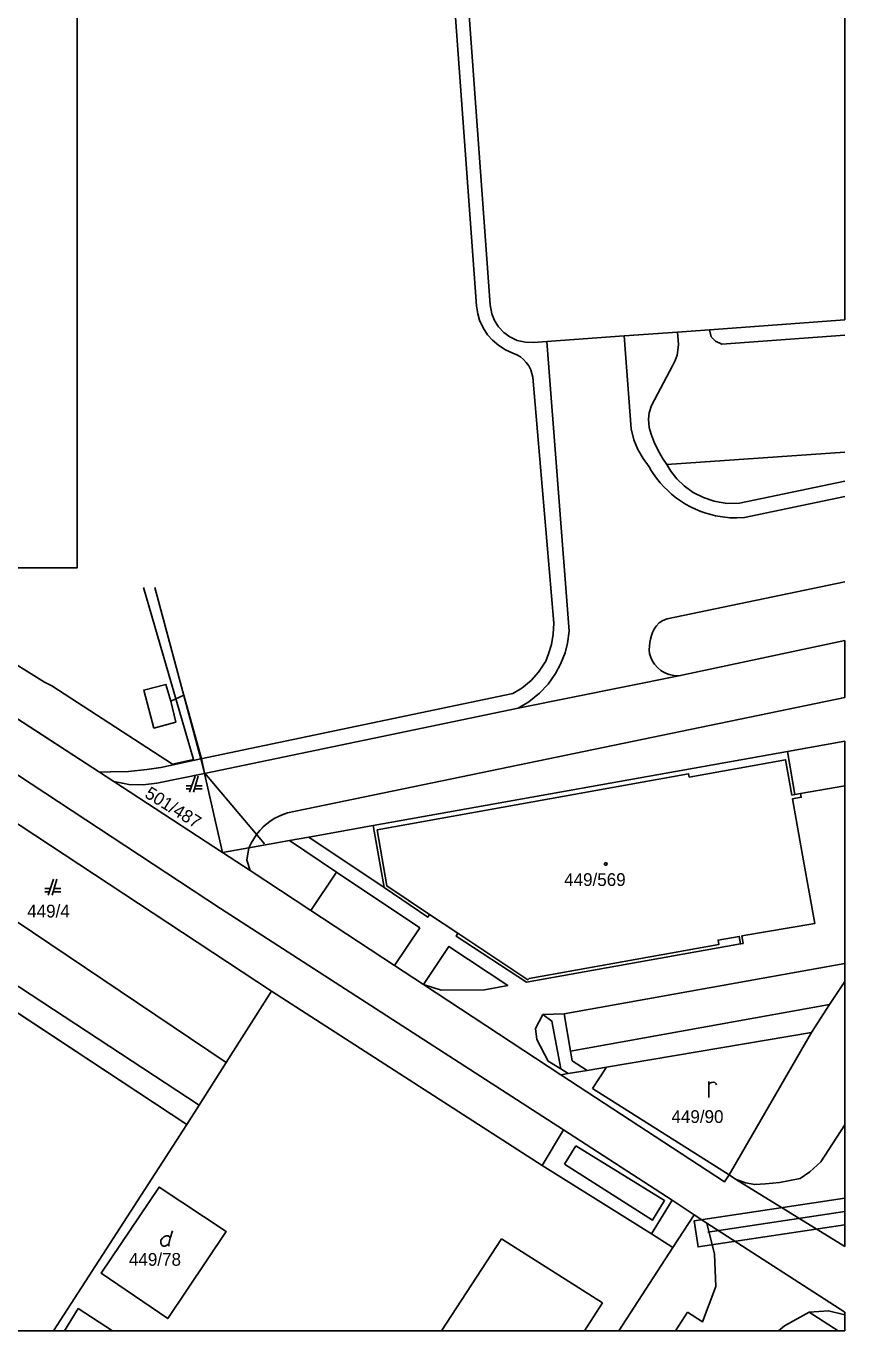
# Model space of a CAD drawing. Extents: x -264309 to -263505, y -1242443 to -1241763.
# Drawn here: x -263692.2 to -263589.3, y -1242443.4 to -1242279.4 of the extents above; entities that cross this region are included whole.
import ezdxf

# ---------------------------------------------------------------- set-up
doc = ezdxf.new("R2010")
doc.units = 0
for name, color, linetype in [('KN_2019_08_16', 7, 'Continuous'), ('KN_2019_08_16_KLADPAR', 7, 'Continuous'), ('KN_2019_08_16_ZAPPAR', 7, 'Continuous'), ('RAM_NA_TLAC_10xA4_1-500', 7, 'Continuous')]:
    doc.layers.add(name, color=color, linetype=linetype)

msp = doc.modelspace()

# ---------------------------------------------------------------- linework, layer by layer
at = {"layer": 'KN_2019_08_16'}
for p, q in [((-263610.2, -1242361.1), (-263589.31, -1242356.66)), ((-263589.31, -1242356.66), (-263589.31, -1242363.85)), ((-263630.41, -1242365.17), (-263610.2, -1242361.1)), ((-263674.06, -1242364.31), (-263672.43, -1242363.55)), ((-263589.31, -1242363.85), (-263659.38, -1242378.34)), ((-263669.82, -1242373.37), (-263630.41, -1242365.17)), ((-263667.55, -1242383.31), (-263669.82, -1242373.37)), ((-263661.45, -1242379.28), (-263662.17, -1242379.84)), ((-263660.98, -1242379), (-263661.45, -1242379.28)), ((-263660.45, -1242378.73), (-263660.98, -1242379)), ((-263659.38, -1242378.34), (-263660.45, -1242378.73)), ((-263663.27, -1242381.05), (-263663.62, -1242381.58)), ((-263662.87, -1242380.54), (-263663.27, -1242381.05)), ((-263662.17, -1242379.84), (-263662.87, -1242380.54)), ((-263664.25, -1242382.72), (-263667.55, -1242383.31)), ((-263663.96, -1242382.14), (-263664.25, -1242382.72)), ((-263663.62, -1242381.58), (-263663.96, -1242382.14))]:
    msp.add_line(p, q, dxfattribs=at)
msp.add_lwpolyline([(-263673.41, -1242366.94), (-263676.19, -1242367.67), (-263677.46, -1242362.89), (-263674.68, -1242362.18), (-263674.06, -1242364.31)], close=True, dxfattribs=at)
for points in [[(-263662.29, -1242382.21), (-263669.81, -1242373.31), (-263670.19, -1242371.53), (-263672.43, -1242363.55)], [(-263683.03, -1242373.21), (-263681.64, -1242373.18), (-263679.37, -1242373.13), (-263677.08, -1242372.9)], [(-263608.27, -1242429.62), (-263589.31, -1242426.78)], [(-263606.54, -1242431.03), (-263589.31, -1242428.45)], [(-263589.31, -1242430.12), (-263607.78, -1242432.89), (-263608.27, -1242429.62)]]:
    msp.add_lwpolyline(points, dxfattribs=at)
at = {"layer": 'KN_2019_08_16_KLADPAR'}
for p, q in [((-263589.31, -1242316.35), (-263589.31, -1242257.5)), ((-263589.31, -1242257.5), (-263589.31, -1242316.35)), ((-263637.43, -1242266.15), (-263633.91, -1242314.48)), ((-263633.91, -1242314.48), (-263637.43, -1242266.15)), ((-263633.91, -1242314.48), (-263633.7, -1242315.61)), ((-263633.7, -1242315.61), (-263633.91, -1242314.48)), ((-263633.7, -1242315.61), (-263633.37, -1242316.46)), ((-263633.37, -1242316.46), (-263633.7, -1242315.61)), ((-263633.37, -1242316.46), (-263632.85, -1242317.25)), ((-263632.85, -1242317.25), (-263633.37, -1242316.46)), ((-263632.85, -1242317.25), (-263632.21, -1242317.94)), ((-263632.21, -1242317.94), (-263632.85, -1242317.25)), ((-263606.35, -1242317.6), (-263589.31, -1242316.35)), ((-263589.31, -1242316.35), (-263606.35, -1242317.6)), ((-263632.21, -1242317.94), (-263631.44, -1242318.5)), ((-263631.44, -1242318.5), (-263632.21, -1242317.94)), ((-263631.44, -1242318.5), (-263630.51, -1242318.94)), ((-263630.51, -1242318.94), (-263631.44, -1242318.5)), ((-263630.51, -1242318.94), (-263629.45, -1242319.18)), ((-263629.45, -1242319.18), (-263630.51, -1242318.94)), ((-263628.43, -1242319.22), (-263626.78, -1242319.09)), ((-263626.78, -1242319.09), (-263628.43, -1242319.22)), ((-263626.78, -1242319.09), (-263617.07, -1242318.38)), ((-263617.07, -1242318.38), (-263626.78, -1242319.09)), ((-263617.07, -1242318.38), (-263610.36, -1242317.89)), ((-263610.36, -1242317.89), (-263617.07, -1242318.38)), ((-263610.36, -1242317.89), (-263606.35, -1242317.6)), ((-263606.35, -1242317.6), (-263610.36, -1242317.89)), ((-263629.45, -1242319.18), (-263628.43, -1242319.22)), ((-263628.43, -1242319.22), (-263629.45, -1242319.18)), ((-263676.05, -1242349.99), (-263670.3, -1242371.56)), ((-263676.05, -1242349.99), (-263670.3, -1242371.56)), ((-263683.03, -1242373.21), (-263697.93, -1242363.54)), ((-263596.55, -1242370.61), (-263589.31, -1242369.32)), ((-263596.55, -1242370.61), (-263589.31, -1242369.32)), ((-263589.31, -1242369.32), (-263589.31, -1242399.51)), ((-263670.3, -1242371.56), (-263675.31, -1242372.61)), ((-263670.3, -1242371.56), (-263670.3, -1242371.56)), ((-263670.3, -1242371.56), (-263669.82, -1242373.37)), ((-263648.63, -1242379.93), (-263596.55, -1242370.61)), ((-263648.63, -1242379.93), (-263596.55, -1242370.61)), ((-263681.64, -1242373.18), (-263683.03, -1242373.21)), ((-263679.37, -1242373.13), (-263681.64, -1242373.18)), ((-263677.08, -1242372.9), (-263679.37, -1242373.13)), ((-263675.31, -1242372.61), (-263677.08, -1242372.9)), ((-263671.01, -1242373.72), (-263671.71, -1242375.72)), ((-263671.21, -1242375.72), (-263670.61, -1242373.72)), ((-263669.82, -1242373.37), (-263667.55, -1242383.31)), ((-263671.43, -1242374.92), (-263672.11, -1242374.92)), ((-263672.11, -1242375.32), (-263671.57, -1242375.32)), ((-263671.09, -1242375.32), (-263670.11, -1242375.32)), ((-263670.11, -1242374.92), (-263670.97, -1242374.92)), ((-263659.13, -1242381.8), (-263656.71, -1242381.37)), ((-263659.13, -1242381.8), (-263656.71, -1242381.37)), ((-263656.71, -1242381.37), (-263648.63, -1242379.93)), ((-263656.71, -1242381.37), (-263648.63, -1242379.93)), ((-263667.55, -1242383.31), (-263664.25, -1242382.72)), ((-263667.55, -1242383.31), (-263664.25, -1242382.72)), ((-263664.25, -1242382.72), (-263659.13, -1242381.8)), ((-263664.25, -1242382.72), (-263659.13, -1242381.8)), ((-263667.55, -1242383.31), (-263667.55, -1242383.31)), ((-263667.55, -1242383.31), (-263667.55, -1242383.31)), ((-263664.1, -1242385.58), (-263667.55, -1242383.31)), ((-263656.46, -1242390.6), (-263664.1, -1242385.58)), ((-263718.68, -1242386.77), (-263672.04, -1242417.52)), ((-263689.21, -1242387.86), (-263689.89, -1242387.86)), ((-263688.79, -1242386.66), (-263689.49, -1242388.66)), ((-263688.99, -1242388.66), (-263688.39, -1242386.66)), ((-263687.89, -1242387.86), (-263688.75, -1242387.86)), ((-263689.89, -1242388.26), (-263689.35, -1242388.26)), ((-263688.87, -1242388.26), (-263687.89, -1242388.26)), ((-263645.94, -1242397.52), (-263656.46, -1242390.6)), ((-263642.28, -1242399.92), (-263645.94, -1242397.52)), ((-263667.1, -1242409.72), (-263661.41, -1242400.75)), ((-263661.41, -1242400.75), (-263661.41, -1242400.75)), ((-263661.41, -1242400.75), (-263661.41, -1242400.75)), ((-263661.41, -1242400.75), (-263661.41, -1242400.75)), ((-263661.41, -1242400.75), (-263661.41, -1242400.75)), ((-263661.41, -1242400.75), (-263661.41, -1242400.75)), ((-263661.41, -1242400.75), (-263627.39, -1242422.66)), ((-263625.01, -1242411.27), (-263642.28, -1242399.92)), ((-263589.31, -1242399.51), (-263591.23, -1242402.42)), ((-263591.23, -1242402.42), (-263589.31, -1242399.51)), ((-263589.31, -1242399.51), (-263589.31, -1242432.83)), ((-263591.23, -1242402.42), (-263593.53, -1242405.92)), ((-263593.53, -1242405.92), (-263591.23, -1242402.42)), ((-263593.53, -1242405.92), (-263619.27, -1242410.29)), ((-263603.88, -1242423.85), (-263593.53, -1242405.92)), ((-263670.49, -1242415.08), (-263667.1, -1242409.72)), ((-263621.71, -1242410.71), (-263624.1, -1242411.11)), ((-263619.27, -1242410.29), (-263621.71, -1242410.71)), ((-263624.1, -1242411.11), (-263625.01, -1242411.27)), ((-263672.04, -1242417.52), (-263670.49, -1242415.08)), ((-263627.39, -1242422.66), (-263613.64, -1242431.25)), ((-263603.08, -1242424.39), (-263603.88, -1242423.85)), ((-263589.31, -1242432.83), (-263603.08, -1242424.39)), ((-263610.94, -1242432.97), (-263608.28, -1242428.86)), ((-263608.28, -1242428.86), (-263606.66, -1242429.9)), ((-263606.66, -1242429.9), (-263589.31, -1242441.09)), ((-263674.12, -1242431.79), (-263673.85, -1242430.89)), ((-263632.48, -1242431.88), (-263640.01, -1242443.45)), ((-263640.01, -1242443.45), (-263632.48, -1242431.88)), ((-263619.78, -1242439.93), (-263632.48, -1242431.88)), ((-263632.48, -1242431.88), (-263619.78, -1242439.93)), ((-263613.64, -1242431.25), (-263610.94, -1242432.97)), ((-263617.74, -1242443.45), (-263610.94, -1242432.97)), ((-263610.94, -1242432.97), (-263617.74, -1242443.45)), ((-263622.04, -1242443.45), (-263619.78, -1242439.93)), ((-263619.78, -1242439.93), (-263622.04, -1242443.45)), ((-263685.72, -1242440.64), (-263687.43, -1242443.45)), ((-263687.43, -1242443.45), (-263685.72, -1242440.64)), ((-263681.39, -1242443.45), (-263685.72, -1242440.64)), ((-263685.72, -1242440.64), (-263681.39, -1242443.45)), ((-263589.31, -1242441.09), (-263589.31, -1242443.45)), ((-263617.74, -1242443.45), (-263755.41, -1242443.45)), ((-263687.43, -1242443.45), (-263681.39, -1242443.45)), ((-263681.39, -1242443.45), (-263687.43, -1242443.45)), ((-263640.01, -1242443.45), (-263622.04, -1242443.45)), ((-263622.04, -1242443.45), (-263640.01, -1242443.45)), ((-263589.31, -1242443.45), (-263617.74, -1242443.45))]:
    msp.add_line(p, q, dxfattribs=at)
for points in [[(-263661.41, -1242400.75), (-263707.9, -1242370.13), (-263738.33, -1242349.99)], [(-263718.47, -1242349.99), (-263697.93, -1242363.54), (-263683.03, -1242373.21), (-263681.22, -1242374.4), (-263667.55, -1242383.31), (-263664.1, -1242385.58), (-263656.46, -1242390.6), (-263645.94, -1242397.52), (-263642.28, -1242399.92), (-263625.01, -1242411.27), (-263604.46, -1242424.73), (-263603.88, -1242423.85), (-263603.08, -1242424.39), (-263589.31, -1242432.83)], [(-263589.31, -1242441.09), (-263606.66, -1242429.9), (-263608.28, -1242428.86), (-263610.94, -1242432.97), (-263613.64, -1242431.25), (-263627.39, -1242422.66), (-263661.41, -1242400.75)], [(-263606.44, -1242414.1), (-263606.44, -1242412.83), (-263606.44, -1242412.1)], [(-263606.44, -1242412.5), (-263606.34, -1242412.37), (-263606.21, -1242412.26), (-263606.07, -1242412.21), (-263605.84, -1242412.2), (-263605.67, -1242412.23), (-263605.57, -1242412.3), (-263605.48, -1242412.4), (-263605.44, -1242412.5)], [(-263674.3, -1242432.78), (-263674.3, -1242432.51), (-263674.12, -1242431.79), (-263674.21, -1242431.61), (-263674.39, -1242431.52), (-263674.66, -1242431.52), (-263674.93, -1242431.61), (-263675.11, -1242431.79), (-263675.29, -1242432.06), (-263675.29, -1242432.42), (-263675.2, -1242432.69), (-263675.02, -1242432.78), (-263674.75, -1242432.78), (-263674.57, -1242432.69), (-263674.3, -1242432.51)]]:
    msp.add_lwpolyline(points, dxfattribs=at)
for points in [[(-263661.41, -1242400.75), (-263667.1, -1242409.72), (-263670.49, -1242415.08), (-263672.04, -1242417.52), (-263718.68, -1242386.77), (-263717.2, -1242384.49), (-263713.38, -1242378.59), (-263707.9, -1242370.13)], [(-263675.31, -1242372.61), (-263670.3, -1242371.56), (-263669.82, -1242373.37), (-263667.55, -1242383.31), (-263681.22, -1242374.4), (-263683.03, -1242373.21), (-263681.64, -1242373.18), (-263679.37, -1242373.13), (-263677.08, -1242372.9)], [(-263596.77, -1242371.66), (-263608.89, -1242373.83), (-263608.96, -1242373.42), (-263648.12, -1242380.47), (-263646.91, -1242387.52), (-263641.52, -1242391.1), (-263637.96, -1242393.47), (-263629.16, -1242399.31), (-263629, -1242399.15), (-263605.15, -1242394.86), (-263605.25, -1242394.32), (-263602.6, -1242393.87), (-263602.43, -1242394.8), (-263602.11, -1242394.74), (-263602.27, -1242393.81), (-263593.11, -1242392.24), (-263594.51, -1242384.36), (-263595.9, -1242376.56), (-263594.8, -1242376.36), (-263594.88, -1242375.91), (-263595.59, -1242376.03), (-263595.98, -1242376.1)], [(-263608.89, -1242373.83), (-263596.77, -1242371.66), (-263595.98, -1242376.1), (-263595.59, -1242376.03), (-263594.88, -1242375.91), (-263594.8, -1242376.36), (-263595.9, -1242376.56), (-263594.51, -1242384.36), (-263593.11, -1242392.24), (-263602.27, -1242393.81), (-263602.11, -1242394.74), (-263602.43, -1242394.8), (-263602.6, -1242393.87), (-263605.25, -1242394.32), (-263605.15, -1242394.86), (-263629, -1242399.15), (-263629.16, -1242399.31), (-263637.96, -1242393.47), (-263641.52, -1242391.1), (-263646.91, -1242387.52), (-263648.12, -1242380.47), (-263608.96, -1242373.42)], [(-263619.29, -1242384.6), (-263619.2, -1242384.75), (-263619.29, -1242384.9), (-263619.47, -1242384.9), (-263619.56, -1242384.75), (-263619.47, -1242384.6)], [(-263625.01, -1242411.27), (-263624.1, -1242411.11), (-263621.71, -1242410.71), (-263619.27, -1242410.29), (-263593.53, -1242405.92), (-263603.88, -1242423.85), (-263604.46, -1242424.73)], [(-263667.11, -1242430.95), (-263675.54, -1242425.37), (-263682.81, -1242436.2), (-263674.45, -1242441.9)], [(-263675.54, -1242425.37), (-263667.11, -1242430.95), (-263674.45, -1242441.9), (-263682.81, -1242436.2)]]:
    msp.add_lwpolyline(points, close=True, dxfattribs=at)
at = {"layer": 'KN_2019_08_16_ZAPPAR'}
for p, q in [((-263626.78, -1242319.09), (-263623.97, -1242355.49)), ((-263604.79, -1242319.42), (-263589.31, -1242318.29)), ((-263628.54, -1242323.56), (-263625.9, -1242354.48)), ((-263589.31, -1242336.63), (-263602.58, -1242339.42)), ((-263601.94, -1242341.21), (-263589.31, -1242338.56)), ((-263673.83, -1242372.23), (-263689.01, -1242362.38)), ((-263596.55, -1242370.61), (-263595.59, -1242376.03)), ((-263677.54, -1242374.83), (-263675.82, -1242374.62)), ((-263675.82, -1242374.62), (-263669.82, -1242373.37)), ((-263667.1, -1242409.72), (-263713.38, -1242378.59)), ((-263656.71, -1242381.37), (-263647.22, -1242387.72)), ((-263648.63, -1242379.93), (-263647.22, -1242387.72)), ((-263664.5, -1242384.28), (-263664.25, -1242382.72)), ((-263653.22, -1242385.77), (-263659.13, -1242381.8)), ((-263670.49, -1242415.08), (-263717.2, -1242384.49)), ((-263664.1, -1242385.58), (-263664.5, -1242384.28)), ((-263656.46, -1242390.6), (-263653.22, -1242385.77)), ((-263642.77, -1242392.78), (-263653.22, -1242385.77)), ((-263645.94, -1242397.52), (-263642.77, -1242392.78)), ((-263602.43, -1242394.8), (-263629.36, -1242399.62)), ((-263589.31, -1242397.26), (-263624.59, -1242403.6)), ((-263640.06, -1242400.63), (-263642.28, -1242399.92)), ((-263634.63, -1242400.56), (-263640.06, -1242400.63)), ((-263591.23, -1242402.42), (-263623.83, -1242408.28)), ((-263624.59, -1242403.6), (-263627.3, -1242403.68)), ((-263628.04, -1242406.8), (-263626.62, -1242409.55)), ((-263626.62, -1242409.55), (-263625.02, -1242410.52)), ((-263621.05, -1242412.99), (-263619.27, -1242410.29)), ((-263603.88, -1242423.85), (-263621.05, -1242412.99)), ((-263672.04, -1242417.52), (-263688.8, -1242443.45)), ((-263627.39, -1242422.66), (-263624.69, -1242418.18)), ((-263589.31, -1242417.56), (-263592.34, -1242422.18)), ((-263624.55, -1242422.5), (-263623.15, -1242420.2)), ((-263613.64, -1242431.25), (-263611.02, -1242427.02)), ((-263609.09, -1242441.11), (-263610.6, -1242443.45))]:
    msp.add_line(p, q, dxfattribs=at)
for points in [[(-263639.05, -1242267.4), (-263635.61, -1242314.61), (-263635.46, -1242315.6), (-263635.23, -1242316.41), (-263634.8, -1242317.36), (-263634.24, -1242318.23), (-263633.62, -1242318.93), (-263632.83, -1242319.6), (-263631.98, -1242320.15), (-263631.05, -1242320.55), (-263630.57, -1242320.74), (-263630.11, -1242321.03), (-263629.7, -1242321.36), (-263629.37, -1242321.73), (-263629.06, -1242322.16), (-263628.81, -1242322.64), (-263628.54, -1242323.56)], [(-263617.07, -1242318.38), (-263616.19, -1242330.08), (-263615.84, -1242331.43), (-263615.33, -1242332.65), (-263614.69, -1242333.78), (-263613.92, -1242334.85), (-263613.66, -1242335.29), (-263613.4, -1242335.69), (-263612.98, -1242336.28), (-263612.55, -1242336.83), (-263612.06, -1242337.36), (-263611.59, -1242337.82), (-263611.12, -1242338.26), (-263610.47, -1242338.79), (-263609.87, -1242339.2), (-263609.35, -1242339.52), (-263608.72, -1242339.87), (-263608.1, -1242340.17), (-263607.41, -1242340.45), (-263606.81, -1242340.66), (-263606.16, -1242340.85), (-263605.57, -1242340.99), (-263604.7, -1242341.14), (-263603.8, -1242341.23), (-263602.92, -1242341.26), (-263601.94, -1242341.21)], [(-263610.36, -1242317.89), (-263610.25, -1242319.48), (-263610.3, -1242320.17), (-263610.42, -1242320.8), (-263610.66, -1242321.48), (-263610.98, -1242322.13), (-263613.64, -1242327.14), (-263613.9, -1242328.03), (-263614, -1242328.85), (-263613.92, -1242329.91), (-263613.69, -1242330.72), (-263613.3, -1242331.72), (-263612.78, -1242332.79), (-263612.25, -1242333.73), (-263611.68, -1242334.53)], [(-263606.35, -1242317.6), (-263606.11, -1242318.5), (-263605.59, -1242319.06), (-263604.79, -1242319.42)], [(-263602.58, -1242339.42), (-263604.15, -1242339.44), (-263605.74, -1242339.17), (-263607.11, -1242338.71), (-263608.39, -1242338.07), (-263609.53, -1242337.24), (-263610.45, -1242336.35), (-263611.21, -1242335.38), (-263611.68, -1242334.53), (-263589.31, -1242333.01)], [(-263677.51, -1242349.99), (-263671.22, -1242371.61), (-263673.83, -1242372.23)], [(-263589.31, -1242356.66), (-263610.2, -1242361.1), (-263610.8, -1242361.08), (-263611.42, -1242360.95), (-263611.96, -1242360.74), (-263612.46, -1242360.44), (-263612.85, -1242360.11), (-263613.24, -1242359.66), (-263613.5, -1242359.25), (-263613.72, -1242358.79), (-263613.86, -1242358.3), (-263613.9, -1242357.84), (-263613.89, -1242357.37), (-263613.83, -1242356.9), (-263613.76, -1242356.49), (-263613.64, -1242356.03), (-263613.49, -1242355.65), (-263613.29, -1242355.23), (-263613.06, -1242354.85), (-263612.67, -1242354.45), (-263612.21, -1242354.15), (-263611.65, -1242353.95), (-263589.31, -1242349.29)], [(-263608.28, -1242428.86), (-263611.02, -1242427.02), (-263624.69, -1242418.18), (-263667.82, -1242390.37), (-263722.21, -1242354.57)], [(-263625.9, -1242354.48), (-263625.98, -1242355.88), (-263626.18, -1242357.16), (-263626.57, -1242358.35), (-263626.92, -1242359.28), (-263627.85, -1242360.64), (-263628.74, -1242361.68), (-263629.92, -1242362.67), (-263631.04, -1242363.35), (-263670.3, -1242371.56)], [(-263623.97, -1242355.49), (-263624.17, -1242357.01), (-263624.48, -1242358.2), (-263625.05, -1242359.66), (-263625.69, -1242360.81), (-263626.62, -1242362.15), (-263627.7, -1242363.29), (-263629.04, -1242364.36), (-263630.41, -1242365.17), (-263669.82, -1242373.37)], [(-263689.01, -1242362.38), (-263689.94, -1242361.92), (-263695.9, -1242358.2), (-263697.39, -1242357.41), (-263698.73, -1242357.59), (-263699.45, -1242358.59), (-263699.3, -1242360.44), (-263698.91, -1242362.05), (-263697.93, -1242363.54)], [(-263589.31, -1242363.85), (-263659.38, -1242378.34), (-263659.99, -1242378.54), (-263660.45, -1242378.73), (-263660.98, -1242379), (-263661.45, -1242379.28), (-263662.17, -1242379.84), (-263662.49, -1242380.13), (-263662.87, -1242380.54), (-263663.27, -1242381.05), (-263663.62, -1242381.58), (-263663.96, -1242382.14), (-263664.25, -1242382.72)], [(-263681.22, -1242374.4), (-263680.14, -1242374.62), (-263679.35, -1242374.75), (-263677.54, -1242374.83)], [(-263594.88, -1242375.91), (-263589.31, -1242374.95)], [(-263647.22, -1242387.72), (-263641.76, -1242391.46), (-263641.52, -1242391.1)], [(-263629.36, -1242399.62), (-263638.2, -1242393.82), (-263637.96, -1242393.47)], [(-263642.28, -1242399.92), (-263639.1, -1242395.11), (-263631.7, -1242400.04), (-263634.63, -1242400.56)], [(-263627.3, -1242403.68), (-263628.19, -1242405.45), (-263628.04, -1242406.8)], [(-263627.3, -1242403.68), (-263626.15, -1242404.5), (-263625.02, -1242410.52), (-263624.1, -1242411.11)], [(-263621.71, -1242410.71), (-263623.58, -1242409.49), (-263623.83, -1242408.28), (-263624.59, -1242403.6)], [(-263623.15, -1242420.2), (-263611.99, -1242427.07), (-263613.49, -1242429.51), (-263624.55, -1242422.5)], [(-263592.34, -1242422.18), (-263593.74, -1242423.46), (-263594.93, -1242424.28), (-263597.55, -1242424.8), (-263599.3, -1242424.95), (-263600.64, -1242425.05), (-263601.82, -1242424.83), (-263603.08, -1242424.39)], [(-263606.66, -1242429.9), (-263605.71, -1242433.8), (-263605.54, -1242437.85), (-263607.21, -1242442.29), (-263609.09, -1242441.11)], [(-263597.66, -1242443.45), (-263596.89, -1242442.8), (-263593.79, -1242441.11), (-263590.16, -1242443.45)], [(-263589.31, -1242441.43), (-263591.36, -1242440.91), (-263593.79, -1242441.11)]]:
    msp.add_lwpolyline(points, dxfattribs=at)
at = {"layer": 'RAM_NA_TLAC_10xA4_1-500'}
msp.add_lwpolyline([(-264210.83, -1242050.54), (-264105.83, -1242050.54), (-264000.83, -1242050.54), (-263895.83, -1242050.54), (-263790.83, -1242050.54), (-263685.83, -1242050.54), (-263685.83, -1242199.04), (-263685.83, -1242347.54), (-263790.83, -1242347.54), (-263895.83, -1242347.54), (-264000.83, -1242347.54), (-264105.83, -1242347.54), (-264210.83, -1242347.54), (-264210.83, -1242199.04)], close=True, dxfattribs=at)

# ---------------------------------------------------------------- texts
at = {"layer": 'KN_2019_08_16_KLADPAR'}
msp.add_text('501/487', height=1.6, rotation=328.1902, dxfattribs=at).set_placement((-263677.46, -1242376.29))
for s, p in [('449/569', (-263624.61, -1242387.52)), ('449/4', (-263692.11, -1242391.48)), ('449/90', (-263611.12, -1242417.31)), ('449/78', (-263679.32, -1242435.26))]:
    msp.add_text(s, height=1.6, dxfattribs=at).set_placement(p)

doc.saveas('drawing.dxf')
